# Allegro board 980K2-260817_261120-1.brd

Outline 419.1 x 474.98 mm; copper layers: TOP, L02_GND, L03_DP, L04_GND, L05_DP, L06_GND, L07_VI, L08_GND, L09_VI, L10_GND, L11_VI, L12_GND, L13_VI, L14_GND, L15_5V, L16_5V, L17_C-BIT, L18_C-BIT, L19_GND, L20_VI, L21_GND, L22_VI, L23_GND, L24_VI, L25_GND, L26_VI, L27_GND, L28_DP, L29_GND, L30_DP, L31_GND, BOTTOM. Coordinates in mm from the lower left corner of the outline.

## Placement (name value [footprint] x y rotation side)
BC9  0.1U-50-X-S4-TDK  [C0402]  86.11 107.82 180 bottom
BR5  1K-1-S4  [R0402]  86.11 106.3 0 bottom
BR6  1K-1-S4  [R0402]  86.11 103.5 0 bottom
BR7  0-5-S6  [R0603]  83.44 106.3 180 bottom
BR8  0-5-S4  [R0402]  86.11 105.03 180 bottom
BR9  0-5-S4  [R0402]  86.11 102.24 180 bottom
BU1  AT24C512C-SSHM-T-SOIC8  [SO8_206X127MM]  91.06 105.66 180 bottom
C48  0.01U-100-X7R-S6-MU  [C0603]  147.57 273.87 90 bottom
C49  0.01U-100-X7R-S6-MU  [C0603]  136.27 268.99 270 bottom
C50  0.01U-100-X7R-S6-MU  [C0603]  142.28 268.54 270 bottom
C53  1U-16-X5R-S4-YA  [C0402]  142.24 261.62 270 bottom
C54  2.2U-16-X-S4-MU  [C0402]  136.53 261.62 270 bottom
C58  1U-16-X5R-S4-YA  [C0402]  142.11 257.68 270 bottom
C59  4.7U-100-X-SB-MU  [C1210]  140.59 246.51 270 bottom
C60  0.01U-100-X7R-S6-MU  [C0603]  147.01 259.72 0 bottom
C61  0.01U-100-X7R-S6-MU  [C0603]  156.88 264.78 180 bottom
C62  2.2U-16-X-S4-MU  [C0402]  157.07 259.72 0 bottom
C63  0.01U-100-X7R-S6-MU  [C0603]  157.73 261.82 90 bottom
C64  0.01U-100-X7R-S6-MU  [C0603]  156.88 267.82 180 bottom
C65  0.1U-25-X7R-S4-MU  [C0402]  157.73 271.37 90 bottom
C66  0.1U-25-X7R-S4-MU  [C0402]  152.65 276.61 180 bottom
C67  0.1U-25-X7R-S4-MU  [C0402]  150.24 278.13 180 bottom
C68  0.1U-25-X7R-S4-MU  [C0402]  147.83 282.7 180 bottom
C69  0.01U-100-X7R-S6-MU  [C0603]  151.96 259.72 0 bottom
C70  0.1U-25-X7R-S4-MU  [C0402]  122.8 294.89 180 bottom
C71  0.1U-25-X7R-S4-MU  [C0402]  129.42 294.89 180 bottom
C72  0.1U-25-X7R-S4-MU  [C0402]  158.75 227.33 0 bottom
C73  0.1U-25-X7R-S4-MU  [C0402]  153.67 227.33 0 bottom
C74  0.1U-25-X7R-S4-MU  [C0402]  157.73 273.91 90 bottom
CT1  47U-16-X5R-SB-MU  [C1210]  88.14 153.16 180 bottom
CT2  10U-16-X5R-S8-TY  [C0805]  108.2 164.59 90 bottom
CT3  22U-16-X-S8-MU  [C0805]  110.49 164.59 90 bottom
CT7  47U-16-X5R-SB-MU  [C1210]  88.14 132.84 180 bottom
CT8  10U-16-X5R-S8-TY  [C0805]  110.49 144.27 90 bottom
CT9  22U-16-X-S8-MU  [C0805]  108.2 144.27 90 bottom
F1  C1F8-0.25A-SA  [FUSE_1206_H1P05MM]  88.14 156.72 0 bottom
F2  C1F8-0.25A-SA  [FUSE_1206_H1P05MM]  88.14 136.4 0 bottom
FD1  -  [FD_040_V2]  95.25 123.19 0 top
FD2  -  [FD_040_V2]  323.85 123.19 0 top
FD3  -  [FD_040_V2]  323.85 351.79 0 top
FD4  -  [FD_040_V2]  95.25 351.79 0 top
FD5  -  [FD_040_V2]  323.85 123.19 180 bottom
FD6  -  [FD_040_V2]  95.25 123.19 180 bottom
FD7  -  [FD_040_V2]  95.25 351.79 180 bottom
FD8  -  [FD_040_V2]  323.85 351.79 180 bottom
FD9  -  [FD_040_V2]  19.05 123.19 0 top
FD10  -  [FD_040_V2]  400.05 123.19 0 top
FD11  -  [FD_040_V2]  400.05 351.79 0 top
FD12  -  [FD_040_V2]  19.05 351.79 0 top
FD13  -  [FD_040_V2]  400.05 123.19 180 bottom
FD14  -  [FD_040_V2]  19.05 123.19 180 bottom
FD15  -  [FD_040_V2]  19.05 351.79 180 bottom
FD16  -  [FD_040_V2]  400.05 351.79 180 bottom
K1  UA2-5NJ-A-V3  [RL_NECUA2_5V_V3]  138.43 290.63 270 bottom
K2  G3VM-201DR  [RL_G3VM201DR_200V]  144.15 277.5 0 bottom
K3  G3VM-201DR  [RL_G3VM201DR_200V]  134.49 273.18 90 bottom
K4  G3VM-201DR  [RL_G3VM201DR_200V]  144.15 291.47 0 bottom
K5  G3VM-51UR-5V-VSON4  [RL_G3VM_4P_VSON4]  139.95 268.99 0 bottom
K6  G3VM-51UR-5V-VSON4  [RL_G3VM_4P_VSON4]  139.95 266.19 0 bottom
K7  G3VM-51UR-5V-VSON4  [RL_G3VM_4P_VSON4]  139.95 264.16 0 bottom
K8  G3VM-51UR-5V-VSON4  [RL_G3VM_4P_VSON4]  139.95 261.62 0 bottom
K9  G3VM-51UR-5V-VSON4  [RL_G3VM_4P_VSON4]  134.24 261.62 0 bottom
K10  G3VM-51UR-5V-VSON4  [RL_G3VM_4P_VSON4]  135.38 264.16 0 bottom
K11  G3VM-51UR-5V-VSON4  [RL_G3VM_4P_VSON4]  143.76 257.3 90 bottom
K12  G3VM-51UR-5V-VSON4  [RL_G3VM_4P_VSON4]  143.76 252.48 90 bottom
K13  G3VM-51UR-5V-VSON4  [RL_G3VM_4P_VSON4]  143.76 246.51 90 bottom
K14  G3VM-51UR-5V-VSON4  [RL_G3VM_4P_VSON4]  146.56 252.48 90 bottom
K15  UA2-5NJ-A-V3  [RL_NECUA2_5V_V3]  135.25 242.75 270 bottom
K16  G3VM-51UR-5V-VSON4  [RL_G3VM_4P_VSON4]  146.56 257.3 90 bottom
K17  G3VM-51UR-5V-VSON4  [RL_G3VM_4P_VSON4]  148.72 257.3 90 bottom
K18  G3VM-51UR-5V-VSON4  [RL_G3VM_4P_VSON4]  148.72 252.48 90 bottom
K19  G3VM-51UR-5V-VSON4  [RL_G3VM_4P_VSON4]  151.51 257.3 90 bottom
K20  G3VM-51UR-5V-VSON4  [RL_G3VM_4P_VSON4]  151.51 252.48 90 bottom
K21  G3VM-51UR-5V-VSON4  [RL_G3VM_4P_VSON4]  153.67 257.3 90 bottom
K22  G3VM-51UR-5V-VSON4  [RL_G3VM_4P_VSON4]  153.67 252.48 90 bottom
K23  UA2-5NJ-A-V3  [RL_NECUA2_5V_V3]  152.78 242.75 270 bottom
K24  UA2-5NJ-A-V3  [RL_NECUA2_5V_V3]  161.04 242.75 270 bottom
K25  G3VM-51UR-5V-VSON4  [RL_G3VM_4P_VSON4]  156.97 257.3 90 bottom
K26  G3VM-51UR-5V-VSON4  [RL_G3VM_4P_VSON4]  156.97 252.48 90 bottom
K27  G3VM-51UR-5V-VSON4  [RL_G3VM_4P_VSON4]  160.15 261.37 180 bottom
K28  G3VM-51UR-5V-VSON4  [RL_G3VM_4P_VSON4]  164.72 261.37 180 bottom
K29  G3VM-51UR-5V-VSON4  [RL_G3VM_4P_VSON4]  169.29 261.37 180 bottom
K30  G3VM-51UR-5V-VSON4  [RL_G3VM_4P_VSON4]  160.15 265.18 180 bottom
K31  G3VM-51UR-5V-VSON4  [RL_G3VM_4P_VSON4]  164.72 265.18 180 bottom
K32  G3VM-51UR-5V-VSON4  [RL_G3VM_4P_VSON4]  169.29 265.18 180 bottom
K33  G3VM-51UR-5V-VSON4  [RL_G3VM_4P_VSON4]  160.15 268.22 180 bottom
K34  G3VM-51UR-5V-VSON4  [RL_G3VM_4P_VSON4]  164.72 268.22 180 bottom
K35  G3VM-51UR-5V-VSON4  [RL_G3VM_4P_VSON4]  169.29 268.22 180 bottom
K36  G3VM-51UR-5V-VSON4  [RL_G3VM_4P_VSON4]  160.15 271.27 180 bottom
K37  G3VM-51UR-5V-VSON4  [RL_G3VM_4P_VSON4]  164.72 271.27 180 bottom
K38  G3VM-51UR-5V-VSON4  [RL_G3VM_4P_VSON4]  160.15 273.81 180 bottom
K39  G3VM-51UR-5V-VSON4  [RL_G3VM_4P_VSON4]  164.72 273.81 180 bottom
K40  G3VM-51UR-5V-VSON4  [RL_G3VM_4P_VSON4]  155.58 273.05 270 bottom
K41  G3VM-51UR-5V-VSON4  [RL_G3VM_4P_VSON4]  155.58 277.62 270 bottom
K42  G3VM-51UR-5V-VSON4  [RL_G3VM_4P_VSON4]  155.58 282.19 270 bottom
K43  G3VM-51UR-5V-VSON4  [RL_G3VM_4P_VSON4]  152.65 273.05 270 bottom
K44  G3VM-51UR-5V-VSON4  [RL_G3VM_4P_VSON4]  152.65 278.89 270 bottom
K45  G3VM-51UR-5V-VSON4  [RL_G3VM_4P_VSON4]  152.65 283.46 270 bottom
K46  G3VM-51UR-5V-VSON4  [RL_G3VM_4P_VSON4]  150.24 274.57 270 bottom
K47  G3VM-51UR-5V-VSON4  [RL_G3VM_4P_VSON4]  150.24 280.42 270 bottom
K48  G3VM-51UR-5V-VSON4  [RL_G3VM_4P_VSON4]  150.24 284.99 270 bottom
K49  G3VM-51UR-5V-VSON4  [RL_G3VM_4P_VSON4]  147.83 284.99 270 bottom
K50  G3VM-51UR-5V-VSON4  [RL_G3VM_4P_VSON4]  147.83 279.15 270 bottom
K51  G3VM-51UR-5V-VSON4  [RL_G3VM_4P_VSON4]  148.72 246.51 270 bottom
K52  G3VM-51UR-5V-VSON4  [RL_G3VM_4P_VSON4]  148.72 241.17 90 bottom
K53  G3VM-51UR-5V-VSON4  [RL_G3VM_4P_VSON4]  156.97 246.51 270 bottom
K54  G3VM-51UR-5V-VSON4  [RL_G3VM_4P_VSON4]  156.97 241.17 90 bottom
K55  G3VM-51UR-5V-VSON4  [RL_G3VM_4P_VSON4]  123.44 292.35 0 bottom
K56  G3VM-201DR  [RL_G3VM201DR_200V]  128.4 288.67 90 bottom
K57  G3VM-51UR-5V-VSON4  [RL_G3VM_4P_VSON4]  158.12 234.57 270 bottom
K58  G3VM-51UR-5V-VSON4  [RL_G3VM_4P_VSON4]  156.08 234.57 270 bottom
K59  G3VM-51UR-5V-VSON4  [RL_G3VM_4P_VSON4]  153.04 234.57 270 bottom
K60  G3VM-51UR-5V-VSON4  [RL_G3VM_4P_VSON4]  151 234.57 270 bottom
K61  G3VM-51UR-5V-VSON4  [RL_G3VM_4P_VSON4]  130.05 292.35 0 bottom
LD1  LDG-2-S6  [LED_0603]  88.91 165.19 0 top
LD3  LDG-2-S6  [LED_0603]  88.91 144.87 0 top
LT1  L10U-16A-S16.5X15.5-PU  [IND_16P5X15P5MM]  98.93 156.59 0 bottom
LT3  L10U-16A-S16.5X15.5-PU  [IND_16P5X15P5MM]  98.93 136.27 0 bottom
M1  PG_LTXDX_F_X1_OUTLINE_TD_V2  [PG_LTXDX_F_X1_OUTLINE_TD_COHU]  209.55 237.49 0 top
NOREF  -  []  222.87 286.99 0 top
NOREF#2  -  []  199.22 255.7 90 top
NOREF#3  -  []  272.63 173.69 0 top
NOREF#4  -  []  312.52 456.29 90 top
NOREF#5  -  []  227.43 224.11 90 top
NOREF#6  -  []  252.87 227.4 90 top
NOREF#7  -  []  198.91 172.21 90 top
NOREF#8  -  []  241.44 244.35 0 top
NOREF#9  -  []  250.92 231.95 90 top
NOREF#10  -  []  151.95 178.07 0 top
NOREF#11  -  []  156.57 253.35 0 top
NOREF#12  -  []  203.84 207.82 90 top
NOREF#13  -  []  157.8 14.59 90 top
NOREF#14  -  []  268.78 222.65 0 top
NOREF#15  -  []  272.25 218.02 0 top
NOREF#16  -  []  196.57 245.63 0 top
NOREF#17  -  []  279.44 239.15 0 top
NOREF#18  -  []  195.17 276.75 90 top
NOREF#19  -  []  188.32 182.05 0 top
NOREF#20  -  []  193.98 238.07 0 top
NOREF#21  -  []  277.18 236.17 90 top
NOREF#22  -  []  160.23 176.17 90 top
NOREF#23  -  []  266.01 250.88 90 top
NOREF#24  -  []  179.72 273.6 90 top
NOREF#25  -  []  138.95 206.12 0 top
NOREF#26  -  []  238.11 172.1 0 top
NOREF#27  -  []  220.83 265.79 90 top
NOREF#28  -  []  260.95 266.12 90 top
NOREF#29  -  []  159.06 238.07 0 top
NOREF#30  -  []  209.52 210.32 90 top
NOREF#31  -  []  190.97 179.57 90 top
NOREF#32  -  []  272.63 173.69 90 top
NOREF#33  -  []  220.95 204.09 90 top
NOREF#34  -  []  239.4 214.54 0 top
NOREF#35  -  []  209.55 237.49 90 top
NOREF#36  -  []  195.92 190.88 90 top
NOREF#37  -  []  273.83 172.21 90 top
NOREF#38  -  []  131.22 234.89 90 top
NOREF#39  -  []  148.19 247.71 0 top
NOREF#40  -  []  156.1 271.85 90 top
NOREF#41  -  []  148.32 242.05 0 top
NOREF#42  -  []  235.49 168.7 90 top
NOREF#43  -  []  197.04 184.35 0 top
NOREF#44  -  []  192.72 192.78 0 top
NOREF#45  -  []  272.66 166.36 90 top
NOREF#46  -  []  283.84 201.77 0 top
NOREF#47  -  []  176.83 287.03 0 top
NOREF#48  -  []  168.45 295.2 0 top
NOREF#49  -  []  159.27 205.58 0 top
NOREF#50  -  []  162.88 458.49 0 top
NOREF#51  -  []  195.92 195.7 90 top
NOREF#52  -  []  191.24 197.85 90 top
NOREF#53  -  []  192.63 172.86 0 top
NOREF#54  -  []  226.01 244.91 90 top
NOREF#55  -  []  218.85 241.15 90 top
NOREF#56  -  []  172.55 190.49 90 top
NOREF#57  -  []  164.44 292.28 90 top
NOREF#58  -  []  204.61 294.89 90 top
NOREF#59  -  []  195.17 276.75 0 top
NOREF#60  -  []  243.84 261.77 0 top
NOREF#61  -  []  236.02 181.47 0 top
NOREF#62  -  []  277.37 256.43 90 top
NOREF#63  -  []  209.55 237.49 0 top
NOREF#64  -  []  209.05 292.28 0 top
NOREF#65  -  []  209.52 204.23 90 top
NOREF#66  -  []  234.39 286.59 90 top
NOREF#67  -  []  230.98 244.35 0 top
NOREF#68  -  []  275.56 235.77 0 top
NOREF#69  -  []  194.39 276.17 90 top
NOREF#70  -  []  283.04 176.5 90 top
NOREF#71  -  []  288.42 267.82 90 top
NOREF#72  -  []  279.72 223.79 90 top
NOREF#73  -  []  251.21 234.89 90 top
NOREF#74  -  []  124.11 392.33 90 top
NOREF#75  -  []  241.75 269.17 0 top
NOREF#76  -  []  196.57 182.05 0 top
NOREF#77  -  []  202.85 297.22 0 top
NOREF#78  -  []  201.75 206.13 0 top
NOREF#79  -  []  283.97 274.54 0 top
NOREF#80  -  []  237.04 184.35 0 top
NOREF#81  -  []  146.88 289.79 0 top
NOREF#82  -  []  156.79 171.3 0 top
NOREF#83  -  []  271.98 280.75 90 top
NOREF#84  -  []  269.12 191.6 90 top
NOREF#85  -  []  199.27 211.67 0 top
NOREF#86  -  []  226.83 256.75 0 top
NOREF#87  -  []  141.55 202.57 90 top
NOREF#88  -  []  224.04 245.96 0 top
NOREF#89  -  []  191.98 286.59 90 top
NOREF#90  -  []  155.96 168.6 90 top
NOREF#91  -  []  151.53 173.37 90 top
NOREF#92  -  []  234.39 222.02 90 top
NOREF#93  -  []  262.81 257.6 0 top
NOREF#94  -  []  140.43 224.38 90 top
NOREF#95  -  []  213.24 201.55 0 top
NOREF#96  -  []  192.51 235.77 0 top
NOREF#97  -  []  226.7 237.02 90 top
NOREF#98  -  []  239.27 270.87 90 top
NOREF#99  -  []  254.09 267.27 90 top
NOREF#100  -  []  152.25 212.18 90 top
NOREF#101  -  []  179.08 201.22 0 top
NOREF#102  -  []  163.97 264.45 90 top
NOREF#103  -  []  279.4 260.64 90 top
NOREF#104  -  []  191.73 172.54 0 top
NOREF#105  -  []  230.41 168.7 90 top
NOREF#106  -  []  189.72 226.19 0 top
NOREF#107  -  []  261.85 306.46 0 top
NOREF#108  -  []  95.33 18.69 0 top
NOREF#109  -  []  220.83 205.79 90 top
NOREF#110  -  []  163.97 213.09 90 top
NOREF#111  -  []  156.33 167.9 90 top
NOREF#112  -  []  185.61 257.6 0 top
NOREF#113  -  []  127.04 239.09 0 top
NOREF#114  -  []  276.61 173.37 90 top
NOREF#115  -  []  179.73 178.35 0 top
NOREF#116  -  []  151.91 191.6 90 top
NOREF#117  -  []  139.55 294.49 0 top
NOREF#118  -  []  155.68 173.69 90 top
NOREF#119  -  []  193.6 286.96 0 top
NOREF#120  -  []  237.25 191.93 0 top
NOREF#121  -  []  218.95 208.91 0 top
NOREF#122  -  []  279.22 195.7 90 top
NOREF#123  -  []  239.4 200.64 90 top
NOREF#124  -  []  190.88 228.6 90 top
NOREF#125  -  []  289.52 212.86 90 top
NOREF#126  -  []  270.97 250.88 90 top
NOREF#127  -  []  228.35 223.79 90 top
NOREF#128  -  []  258.95 264.09 0 top
NOREF#129  -  []  271.11 193.35 0 top
NOREF#130  -  []  283.97 207.5 90 top
NOREF#131  -  []  149.55 188.99 90 top
NOREF#132  -  []  219.08 201.22 0 top
NOREF#133  -  []  268.44 257.85 90 top
NOREF#134  -  []  231.53 233.37 90 top
NOREF#135  -  []  228.78 244.35 0 top
NOREF#136  -  []  197.71 173.69 0 top
NOREF#137  -  []  153.18 271.85 90 top
NOREF#138  -  []  243.84 204.78 90 top
NOREF#139  -  []  268.78 184.35 0 top
NOREF#140  -  []  244.32 291.95 90 top
NOREF#141  -  []  149.29 279.37 0 top
NOREF#142  -  []  294.99 82.65 0 top
NOREF#143  -  []  267.77 257.6 0 top
NOREF#144  -  []  206.32 274.76 0 top
NOREF#145  -  []  165.38 286.23 0 top
NOREF#146  -  []  132.26 248.4 0 top
NOREF#147  -  []  159.4 212 0 top
NOREF#148  -  []  169.52 210.32 90 top
NOREF#149  -  []  214.51 203.76 0 top
NOREF#150  -  []  196.1 211.85 90 top
NOREF#151  -  []  146.83 191.93 0 top
NOREF#152  -  []  218.95 206.12 0 top
NOREF#153  -  []  172.87 287.4 90 top
NOREF#154  -  []  152.46 247.68 90 top
NOREF#155  -  []  273.18 184.35 0 top
NOREF#156  -  []  58.41 375.29 0 top
NOREF#157  -  []  222.81 197.6 0 top
NOREF#158  -  []  293.99 17.15 90 top
NOREF#159  -  []  193.27 253.35 0 top
NOREF#160  -  []  186.28 253.03 90 top
NOREF#161  -  []  219.55 180.49 90 top
NOREF#162  -  []  237.25 240.62 0 top
NOREF#163  -  []  146.28 193.03 90 top
NOREF#164  -  []  163.84 267.82 90 top
NOREF#165  -  []  309.55 14.59 90 top
NOREF#166  -  []  275.68 173.69 0 top
NOREF#167  -  []  175.11 261.22 90 top
NOREF#168  -  []  243.97 274.54 0 top
NOREF#169  -  []  290.89 209.17 0 top
NOREF#170  -  []  150.41 228.7 90 top
NOREF#171  -  []  271.19 228.49 0 top
NOREF#172  -  []  150.77 279.22 90 top
NOREF#173  -  []  278.91 232.21 90 top
NOREF#174  -  []  182.87 286.99 0 top
NOREF#175  -  []  197.92 250.01 0 top
NOREF#176  -  []  283.04 236.5 90 top
NOREF#177  -  []  270.77 219.22 90 top
NOREF#178  -  []  268.32 185.63 90 top
NOREF#179  -  []  140.59 184.98 90 top
NOREF#180  -  []  269.72 281.62 0 top
NOREF#181  -  []  181.6 308.11 0 top
NOREF#182  -  []  130.02 214.45 0 top
NOREF#183  -  []  276.02 181.47 0 top
NOREF#184  -  []  193.76 195.7 90 top
NOREF#185  -  []  243.84 273.41 90 top
NOREF#186  -  []  152.51 235.77 0 top
NOREF#187  -  []  144.71 241.71 90 top
NOREF#188  -  []  181.55 267.14 90 top
NOREF#189  -  []  181.55 265.11 90 top
NOREF#190  -  []  163.84 274.21 0 top
NOREF#191  -  []  129.17 291.95 0 top
NOREF#192  -  []  199.4 205.9 0 top
NOREF#193  -  []  254.09 200.42 90 top
NOREF#194  -  []  147.77 197.6 0 top
NOREF#195  -  []  197.37 251.6 90 top
NOREF#196  -  []  228.32 185.63 90 top
NOREF#197  -  []  218.95 264.09 0 top
NOREF#198  -  []  148.99 240.62 0 top
NOREF#199  -  []  149.67 190.01 0 top
NOREF#200  -  []  271.76 227.33 0 top
NOREF#201  -  []  199.4 260.64 90 top
NOREF#202  -  []  272.72 197.6 0 top
NOREF#203  -  []  199.22 195.7 90 top
NOREF#204  -  []  236.81 232.54 0 top
NOREF#205  -  []  197.03 238.07 0 top
NOREF#206  -  []  288.54 202.09 0 top
NOREF#207  -  []  181.55 207.14 90 top
NOREF#208  -  []  147.3 220.35 0 top
NOREF#209  -  []  276.7 181.72 90 top
NOREF#210  -  []  188.99 251.93 0 top
NOREF#211  -  []  271.95 238.07 0 top
NOREF#212  -  []  146.7 237.02 90 top
NOREF#213  -  []  269.72 215.77 0 top
NOREF#214  -  []  145.61 252.5 0 top
NOREF#215  -  []  197.47 17.15 90 top
NOREF#216  -  []  227.43 284.11 0 top
NOREF#217  -  []  271.24 253.03 90 top
NOREF#218  -  []  225.41 213.02 90 top
NOREF#219  -  []  264.26 396.29 0 top
NOREF#220  -  []  216.55 220.49 0 top
NOREF#221  -  []  266.69 297.01 90 top
NOREF#222  -  []  159.27 270.87 90 top
NOREF#223  -  []  229.84 213.7 90 top
NOREF#224  -  []  156.57 245.63 0 top
NOREF#225  -  []  179.08 263.76 0 top
NOREF#226  -  []  148.78 244.35 0 top
NOREF#227  -  []  195.05 278.82 0 top
NOREF#228  -  []  232.13 280.09 0 top
NOREF#229  -  []  191.87 456.29 90 top
NOREF#230  -  []  266.16 198.18 0 top
NOREF#231  -  []  151.19 228.49 0 top
NOREF#232  -  []  264.26 456.29 90 top
NOREF#233  -  []  215.65 244.35 0 top
NOREF#234  -  []  219.73 178.35 0 top
NOREF#235  -  []  89.76 145.32 0 top
NOREF#236  -  []  266.43 296.46 90 top
NOREF#237  -  []  165.38 286.23 0 top
NOREF#238  -  []  231.98 286.59 90 top
NOREF#239  -  []  203.4 236.38 0 top
NOREF#240  -  []  283.97 200.64 90 top
NOREF#241  -  []  194.33 264.33 90 top
NOREF#242  -  []  234.39 276.17 90 top
NOREF#243  -  []  234.07 256.43 90 top
NOREF#244  -  []  243.97 273.09 90 top
NOREF#245  -  []  195.68 173.69 0 top
NOREF#246  -  []  276.54 167 0 top
NOREF#247  -  []  178.95 208.91 0 top
NOREF#248  -  []  153.27 193.35 0 top
NOREF#249  -  []  242.2 238.35 0 top
NOREF#250  -  []  271.11 253.35 0 top
NOREF#251  -  []  136.28 307.18 0 top
NOREF#252  -  []  239.44 179.15 0 top
NOREF#253  -  []  191.98 226.59 90 top
NOREF#254  -  []  256.83 227.03 0 top
NOREF#255  -  []  199.72 223.79 90 top
NOREF#256  -  []  152.25 272.17 0 top
NOREF#257  -  []  294.09 264.23 90 top
NOREF#258  -  []  173.45 244.35 0 top
NOREF#259  -  []  149.72 275.77 0 top
NOREF#260  -  []  162.87 16.49 0 top
NOREF#261  -  []  218.35 209.04 0 top
NOREF#262  -  []  219.08 268.59 0 top
NOREF#263  -  []  254.09 204.23 90 top
NOREF#264  -  []  261.59 294.14 0 top
NOREF#265  -  []  268.78 288.49 0 top
NOREF#266  -  []  173.78 267.01 0 top
NOREF#267  -  []  267.05 209.24 0 top
NOREF#268  -  []  231.91 191.6 90 top
NOREF#269  -  []  229.72 226.19 0 top
NOREF#270  -  []  196.7 241.72 90 top
NOREF#271  -  []  261.55 269.94 90 top
NOREF#272  -  []  186.01 244.91 90 top
NOREF#273  -  []  183.36 193.35 0 top
NOREF#274  -  []  193.76 250.88 90 top
NOREF#275  -  []  147.9 205.84 90 top
NOREF#276  -  []  272.51 175.77 0 top
NOREF#277  -  []  230.77 223.79 90 top
NOREF#278  -  []  232.25 222.59 0 top
NOREF#279  -  []  267.05 269.24 0 top
NOREF#280  -  []  151.11 258.18 0 top
NOREF#281  -  []  215.11 261.22 90 top
NOREF#282  -  []  180.95 204.09 90 top
NOREF#283  -  []  151.79 191.93 0 top
NOREF#284  -  []  273.03 172.1 0 top
NOREF#285  -  []  151.7 277.85 0 top
NOREF#286  -  []  195.17 281.32 90 top
NOREF#287  -  []  196.79 171.3 0 top
NOREF#288  -  []  159.4 260.64 90 top
NOREF#289  -  []  275.17 281.32 90 top
NOREF#290  -  []  192.25 222.59 90 top
NOREF#291  -  []  231.19 218.07 0 top
NOREF#292  -  []  147.3 280.35 0 top
NOREF#293  -  []  187.43 278.27 90 top
NOREF#294  -  []  186.96 251.6 90 top
NOREF#295  -  []  232.25 282.59 90 top
NOREF#296  -  []  142.81 241.71 0 top
NOREF#297  -  []  233.6 282.39 0 top
NOREF#298  -  []  199.4 204.45 90 top
NOREF#299  -  []  231.11 198.18 0 top
NOREF#300  -  []  228.99 191.93 0 top
NOREF#301  -  []  146.83 256.75 0 top
NOREF#302  -  []  170.89 206.13 0 top
NOREF#303  -  []  286.32 214.76 0 top
NOREF#304  -  []  286.32 212.22 0 top
NOREF#305  -  []  272.25 212.18 0 top
NOREF#306  -  []  286.32 266.13 0 top
NOREF#307  -  []  218.83 232.23 0 top
NOREF#308  -  []  148.78 222.65 0 top
NOREF#309  -  []  176.55 280.49 0 top
NOREF#310  -  []  233.76 250.88 90 top
NOREF#311  -  []  157.71 173.69 0 top
NOREF#312  -  []  271.76 167.33 0 top
NOREF#313  -  []  139.08 263.76 0 top
NOREF#314  -  []  188.19 247.71 0 top
NOREF#315  -  []  227.03 231.4 0 top
NOREF#316  -  []  167.04 239.09 0 top
NOREF#317  -  []  210.89 206.13 0 top
NOREF#318  -  []  187.99 238.35 0 top
NOREF#319  -  []  180.43 224.38 90 top
NOREF#320  -  []  157.04 244.35 0 top
NOREF#321  -  []  284.95 272.86 90 top
NOREF#322  -  []  255.11 201.22 90 top
NOREF#323  -  []  248.45 295.2 0 top
NOREF#324  -  []  208.42 260.97 90 top
NOREF#325  -  []  188.78 184.35 0 top
NOREF#326  -  []  214.43 292.23 0 top
NOREF#327  -  []  241.75 274.76 0 top
NOREF#328  -  []  138.95 261.55 0 top
NOREF#329  -  []  136.5 271.94 90 top
NOREF#330  -  []  232.25 272.17 0 top
NOREF#331  -  []  193.03 172.1 0 top
NOREF#332  -  []  89.76 164.74 90 top
NOREF#333  -  []  139.55 240.49 90 top
NOREF#334  -  []  220.59 244.98 90 top
NOREF#335  -  []  132.55 190.49 90 top
NOREF#336  -  []  261.59 308.11 0 top
NOREF#337  -  []  181.85 292.49 0 top
NOREF#338  -  []  156.02 247.68 0 top
NOREF#339  -  []  276.8 280.49 90 top
NOREF#340  -  []  156.81 232.54 0 top
NOREF#341  -  []  135.43 276.18 0 top
NOREF#342  -  []  164.95 207.27 90 top
NOREF#343  -  []  283.97 205.9 0 top
NOREF#344  -  []  163.97 273.09 90 top
NOREF#345  -  []  155.78 237.5 90 top
NOREF#346  -  []  266.83 256.75 0 top
NOREF#347  -  []  275.05 214.25 0 top
NOREF#348  -  []  161.84 295.2 0 top
NOREF#349  -  []  239.4 202.09 0 top
NOREF#350  -  []  192.63 232.86 0 top
NOREF#351  -  []  156.33 227.9 90 top
NOREF#352  -  []  219.73 238.35 0 top
NOREF#353  -  []  268.81 250.88 90 top
NOREF#354  -  []  199.27 200.97 90 top
NOREF#355  -  []  133.36 261.22 0 top
NOREF#356  -  []  227.3 220.35 0 top
NOREF#357  -  []  197.47 17.15 0 top
NOREF#358  -  []  228.35 217.95 90 top
NOREF#359  -  []  192.72 252.78 0 top
NOREF#360  -  []  276.7 253.03 90 top
NOREF#361  -  []  266.96 191.6 90 top
NOREF#362  -  []  155.56 235.77 0 top
NOREF#363  -  []  270.15 266.89 90 top
NOREF#364  -  []  220.95 266.12 90 top
NOREF#365  -  []  150.63 259.3 0 top
NOREF#366  -  []  159.06 178.07 0 top
NOREF#367  -  []  288.54 265.9 0 top
NOREF#368  -  []  246.32 274.76 0 top
NOREF#369  -  []  277.37 191.6 90 top
NOREF#370  -  []  226.01 184.91 90 top
NOREF#371  -  []  134.04 210.63 90 top
NOREF#372  -  []  151.7 283.69 0 top
NOREF#373  -  []  159.4 273.09 90 top
NOREF#374  -  []  193.6 226.96 0 top
NOREF#375  -  []  318.12 17.15 0 top
NOREF#376  -  []  149.29 282.02 90 top
NOREF#377  -  []  138.95 268.91 0 top
NOREF#378  -  []  232.13 224.66 0 top
NOREF#379  -  []  159.4 268.95 0 top
NOREF#380  -  []  227.77 257.6 0 top
NOREF#381  -  []  283.84 213.41 90 top
NOREF#382  -  []  211.21 294.89 90 top
NOREF#383  -  []  239.27 200.97 90 top
NOREF#384  -  []  239.44 239.15 0 top
NOREF#385  -  []  277.25 251.93 0 top
NOREF#386  -  []  250.89 262.32 0 top
NOREF#387  -  []  159.72 223.79 90 top
NOREF#388  -  []  288.42 260.97 90 top
NOREF#389  -  []  231.19 223.92 0 top
NOREF#390  -  []  277.5 245.31 90 top
NOREF#391  -  []  283.97 264.45 90 top
NOREF#392  -  []  137.28 272.5 90 top
NOREF#393  -  []  214.43 232.23 0 top
NOREF#394  -  []  279.4 210.55 90 top
NOREF#395  -  []  155.68 233.69 0 top
NOREF#396  -  []  155.17 281.32 90 top
NOREF#397  -  []  152.63 233.69 0 top
NOREF#398  -  []  268.44 181.72 90 top
NOREF#399  -  []  219.73 178.35 0 top
NOREF#400  -  []  106.83 127.87 90 top
NOREF#401  -  []  199.27 207.82 90 top
NOREF#402  -  []  137.28 286.47 90 top
NOREF#403  -  []  164.95 270.32 90 top
NOREF#404  -  []  236.38 181.15 90 top
NOREF#405  -  []  192.51 175.77 0 top
NOREF#406  -  []  167.98 226.38 90 top
NOREF#407  -  []  294.09 204.23 90 top
NOREF#408  -  []  209.49 220.89 0 top
NOREF#409  -  []  199.4 213.09 90 top
NOREF#410  -  []  262.87 213.02 0 top
NOREF#411  -  []  225 456.29 0 top
NOREF#412  -  []  194.39 286.59 90 top
NOREF#413  -  []  171.22 234.89 90 top
NOREF#414  -  []  185.41 226.99 90 top
NOREF#415  -  []  136.26 263.76 90 top
NOREF#416  -  []  196.57 258.18 0 top
NOREF#417  -  []  156.02 248.11 90 top
NOREF#418  -  []  243.84 205.58 0 top
NOREF#419  -  []  203.97 264.45 90 top
NOREF#420  -  []  190.56 257.6 0 top
NOREF#421  -  []  192.63 173.69 90 top
NOREF#422  -  []  83.04 144.22 90 top
NOREF#423  -  []  201.75 214.76 0 top
NOREF#424  -  []  155.17 276.75 90 top
NOREF#425  -  []  227.99 178.35 0 top
NOREF#426  -  []  186.43 222.5 90 top
NOREF#427  -  []  195.68 233.69 0 top
NOREF#428  -  []  143.36 253.35 0 top
NOREF#429  -  []  180.83 205.79 90 top
NOREF#430  -  []  233.18 184.35 0 top
NOREF#431  -  []  143.61 456.29 90 top
NOREF#432  -  []  174.09 200.42 90 top
NOREF#433  -  []  153.56 233.37 90 top
NOREF#434  -  []  271.73 172.54 0 top
NOREF#435  -  []  199.22 190.88 90 top
NOREF#436  -  []  234.33 267.37 90 top
NOREF#437  -  []  228.32 245.63 90 top
NOREF#438  -  []  175.24 201.55 90 top
NOREF#439  -  []  190.56 192.78 0 top
NOREF#440  -  []  161.41 167.9 90 top
NOREF#441  -  []  191.24 253.03 90 top
NOREF#442  -  []  168.42 208.62 0 top
NOREF#443  -  []  201.41 167.9 90 top
NOREF#444  -  []  192.63 233.69 90 top
NOREF#445  -  []  159.27 208.62 0 top
NOREF#446  -  []  235.58 202.67 90 top
NOREF#447  -  []  146.16 253.35 0 top
NOREF#448  -  []  265.61 192.78 0 top
NOREF#449  -  []  226.16 212.17 90 top
NOREF#450  -  []  156.38 241.15 90 top
NOREF#451  -  []  233.56 173.37 90 top
NOREF#452  -  []  279.27 267.82 90 top
NOREF#453  -  []  184.04 191.93 0 top
NOREF#454  -  []  232.51 235.77 0 top
NOREF#455  -  []  237.37 240.3 90 top
NOREF#456  -  []  117.23 452.29 90 top
NOREF#457  -  []  249.17 291.95 0 top
NOREF#458  -  []  257.29 187.78 0 top
NOREF#459  -  []  289.52 272.86 90 top
NOREF#460  -  []  284.95 204.23 90 top
NOREF#461  -  []  158.04 228.3 0 top
NOREF#462  -  []  85.84 137.3 0 top
NOREF#463  -  []  150.6 173.69 90 top
NOREF#464  -  []  170.02 274.45 0 top
NOREF#465  -  []  248.42 265.58 0 top
NOREF#466  -  []  164.95 264.23 90 top
NOREF#467  -  []  277.59 235.77 0 top
NOREF#468  -  []  147.77 236.37 0 top
NOREF#469  -  []  186.01 190.88 90 top
NOREF#470  -  []  273.39 193.03 90 top
NOREF#471  -  []  267.99 238.35 0 top
NOREF#472  -  []  156.7 193.03 90 top
NOREF#473  -  []  156.7 253.03 90 top
NOREF#474  -  []  194.33 207.37 90 top
NOREF#475  -  []  284.95 212.86 90 top
NOREF#476  -  []  193.95 191.93 0 top
NOREF#477  -  []  235.17 281.32 90 top
NOREF#478  -  []  186.7 223.05 90 top
NOREF#479  -  []  154.63 282.42 0 top
NOREF#480  -  []  138.95 266.12 0 top
NOREF#481  -  []  149.24 245.31 90 top
NOREF#482  -  []  187.45 269.24 0 top
NOREF#483  -  []  236.57 245.63 0 top
NOREF#484  -  []  277.92 190.01 0 top
NOREF#485  -  []  286.32 272.22 0 top
NOREF#486  -  []  183.36 258.18 0 top
NOREF#487  -  []  279.27 205.58 0 top
NOREF#488  -  []  167.95 226.12 90 top
NOREF#489  -  []  114.62 458.49 0 top
NOREF#490  -  []  201.44 184.35 0 top
NOREF#491  -  []  154.33 264.33 90 top
NOREF#492  -  []  181.55 209.94 90 top
NOREF#493  -  []  146.28 197.85 90 top
NOREF#494  -  []  273.18 271.85 90 top
NOREF#495  -  []  139.49 266.31 90 top
NOREF#496  -  []  158.11 232.1 0 top
NOREF#497  -  []  216 396.29 0 top
NOREF#498  -  []  186.7 283.04 90 top
NOREF#499  -  []  259.55 180.49 90 top
NOREF#500  -  []  193.76 255.7 90 top
NOREF#501  -  []  252.55 190.49 90 top
NOREF#502  -  []  197.25 251.93 0 top
NOREF#503  -  []  149.84 284.11 90 top
NOREF#504  -  []  192.13 214.25 0 top
NOREF#505  -  []  272.13 224.66 0 top
NOREF#506  -  []  270.97 179.57 90 top
NOREF#507  -  []  153.18 244.35 0 top
NOREF#508  -  []  196.52 221.12 0 top
NOREF#509  -  []  209.55 237.49 90 top
NOREF#510  -  []  189.84 284.11 90 top
NOREF#511  -  []  203.97 212 0 top
NOREF#512  -  []  258.35 204.47 0 top
NOREF#513  -  []  233.39 257.85 90 top
NOREF#514  -  []  148.32 182.05 0 top
NOREF#515  -  []  218.95 268.91 0 top
NOREF#516  -  []  197.18 236.17 90 top
NOREF#517  -  []  244.32 231.95 90 top
NOREF#518  -  []  202.2 238.35 0 top
NOREF#519  -  []  235.68 173.69 90 top
NOREF#520  -  []  203.84 201.77 0 top
NOREF#521  -  []  208.54 260.64 90 top
NOREF#522  -  []  238.64 233.37 90 top
NOREF#523  -  []  163.84 205.58 0 top
NOREF#524  -  []  188.35 283.79 90 top
NOREF#525  -  []  294.09 207.27 90 top
NOREF#526  -  []  275.56 175.77 0 top
NOREF#527  -  []  172.55 224.49 0 top
NOREF#528  -  []  196.02 197.6 0 top
NOREF#529  -  []  140.95 206.12 90 top
NOREF#530  -  []  140.83 208.59 90 top
NOREF#531  -  []  150.48 175.77 0 top
NOREF#532  -  []  276.7 241.72 90 top
NOREF#533  -  []  239.22 179.57 90 top
NOREF#534  -  []  155.97 21.69 90 top
NOREF#535  -  []  260.83 261.22 90 top
NOREF#536  -  []  134.51 263.76 0 top
NOREF#537  -  []  149.72 286.19 0 top
NOREF#538  -  []  154.63 283.79 90 top
NOREF#539  -  []  133.24 261.55 0 top
NOREF#540  -  []  221.59 294.14 0 top
NOREF#541  -  []  233.18 282.26 90 top
NOREF#542  -  []  234.07 251.6 90 top
NOREF#543  -  []  182.81 246.81 0 top
NOREF#544  -  []  201.75 202.32 0 top
NOREF#545  -  []  184.04 196.75 0 top
NOREF#546  -  []  149.21 17.15 0 top
NOREF#547  -  []  279.27 201.77 0 top
NOREF#548  -  []  147.77 251.31 0 top
NOREF#549  -  []  199.06 178.07 0 top
NOREF#550  -  []  281.75 212.22 0 top
NOREF#551  -  []  243.84 268.62 0 top
NOREF#552  -  []  227.45 269.24 0 top
NOREF#553  -  []  134.43 292.23 0 top
NOREF#554  -  []  243.04 236.5 90 top
NOREF#555  -  []  114.55 316.49 0 top
NOREF#556  -  []  219.72 273.6 90 top
NOREF#557  -  []  228.32 193.35 0 top
NOREF#558  -  []  242.44 292.28 0 top
NOREF#559  -  []  147.43 218.27 0 top
NOREF#560  -  []  203.1 18.69 90 top
NOREF#561  -  []  277.25 240.62 0 top
NOREF#562  -  []  163.97 205.9 0 top
NOREF#563  -  []  243.97 262.09 0 top
NOREF#564  -  []  270.15 206.89 90 top
NOREF#565  -  []  270.98 184.35 0 top
NOREF#566  -  []  239.27 273.41 90 top
NOREF#567  -  []  254.09 207.27 90 top
NOREF#568  -  []  230.88 168.6 90 top
NOREF#569  -  []  213.36 201.22 0 top
NOREF#570  -  []  205.38 226.23 0 top
NOREF#571  -  []  209.55 237.49 0 top
NOREF#572  -  []  236.7 197.85 90 top
NOREF#573  -  []  217.29 187.78 0 top
NOREF#574  -  []  201.75 209.17 0 top
NOREF#575  -  []  185.09 197.49 90 top
NOREF#576  -  []  168.54 205.9 0 top
NOREF#577  -  []  264.16 245.63 90 top
NOREF#578  -  []  150.77 273.37 90 top
NOREF#579  -  []  161.75 274.76 0 top
NOREF#580  -  []  157.71 233.69 90 top
NOREF#581  -  []  266.69 283.04 90 top
NOREF#582  -  []  258.95 201.55 0 top
NOREF#583  -  []  266.01 244.91 90 top
NOREF#584  -  []  148.35 277.95 90 top
NOREF#585  -  []  129.44 260.67 0 top
NOREF#586  -  []  273.94 251.93 0 top
NOREF#587  -  []  268.78 282.65 0 top
NOREF#588  -  []  223.49 187.06 90 top
NOREF#589  -  []  159.4 272 0 top
NOREF#590  -  []  256.98 265.11 90 top
NOREF#591  -  []  226.43 222.5 90 top
NOREF#592  -  []  191.11 198.18 0 top
NOREF#593  -  []  216.98 265.11 90 top
NOREF#594  -  []  193.6 276.55 0 top
NOREF#595  -  []  259.08 201.22 0 top
NOREF#596  -  []  279.4 262.09 0 top
NOREF#597  -  []  163.97 270.55 90 top
NOREF#598  -  []  203.97 202.09 0 top
NOREF#599  -  []  226.7 223.05 90 top
NOREF#600  -  []  189.72 286.19 0 top
NOREF#601  -  []  147.3 226.19 0 top
NOREF#602  -  []  155.05 214.25 0 top
NOREF#603  -  []  190.97 190.88 90 top
NOREF#604  -  []  283.84 273.41 90 top
NOREF#605  -  []  263.49 257.85 90 top
NOREF#606  -  []  187.77 257.6 0 top
NOREF#607  -  []  193.18 277.69 90 top
NOREF#608  -  []  187.01 458.49 0 top
NOREF#609  -  []  145.42 273.02 90 top
NOREF#610  -  []  135.15 265.24 90 top
NOREF#611  -  []  149.84 213.7 90 top
NOREF#612  -  []  146.17 212.17 90 top
NOREF#613  -  []  189.72 275.77 0 top
NOREF#614  -  []  230.88 228.6 90 top
NOREF#615  -  []  135.24 261.55 90 top
NOREF#616  -  []  239.4 210.55 90 top
NOREF#617  -  []  171.05 229.49 0 top
NOREF#618  -  []  129.17 231.95 0 top
NOREF#619  -  []  171.22 234.24 90 top
NOREF#620  -  []  239.72 214.65 90 top
NOREF#621  -  []  228.44 241.72 90 top
NOREF#622  -  []  276.52 281.12 0 top
NOREF#623  -  []  188.78 244.35 0 top
NOREF#624  -  []  156.45 187.71 0 top
NOREF#625  -  []  241.41 227.9 90 top
NOREF#626  -  []  243.97 205.9 0 top
NOREF#627  -  []  157.03 178.07 0 top
NOREF#628  -  []  239.27 211.67 0 top
NOREF#629  -  []  239.4 264.45 90 top
NOREF#630  -  []  152.51 175.77 0 top
NOREF#631  -  []  239.65 272.56 0 top
NOREF#632  -  []  156.57 242.05 0 top
NOREF#633  -  []  208.42 264.78 90 top
NOREF#634  -  []  174.43 232.23 0 top
NOREF#635  -  []  193.6 216.55 0 top
NOREF#636  -  []  146.88 283.95 0 top
NOREF#637  -  []  154.33 204.33 90 top
NOREF#638  -  []  267.8 205.39 90 top
NOREF#639  -  []  260.95 201.55 90 top
NOREF#640  -  []  140.83 268.59 90 top
NOREF#641  -  []  188.32 242.05 0 top
NOREF#642  -  []  273.27 193.35 0 top
NOREF#643  -  []  216 456.29 0 top
NOREF#644  -  []  230.97 190.88 90 top
NOREF#645  -  []  186.01 250.88 90 top
NOREF#646  -  []  248.54 208.95 0 top
NOREF#647  -  []  152.25 218.02 0 top
NOREF#648  -  []  266.16 212.17 90 top
NOREF#649  -  []  184.16 196.43 90 top
NOREF#650  -  []  156.8 225.06 90 top
NOREF#651  -  []  233.6 216.55 0 top
NOREF#652  -  []  237.71 172.86 0 top
NOREF#653  -  []  151.19 223.92 0 top
NOREF#654  -  []  180.83 208.59 90 top
NOREF#655  -  []  203.84 274.21 0 top
NOREF#656  -  []  161.44 184.35 0 top
NOREF#657  -  []  243.84 265.58 0 top
NOREF#658  -  []  236.54 227 0 top
NOREF#659  -  []  146.83 251.93 0 top
NOREF#660  -  []  195.17 221.32 0 top
NOREF#661  -  []  195.17 212.18 90 top
NOREF#662  -  []  150.88 168.6 90 top
NOREF#663  -  []  284.95 270.32 90 top
NOREF#664  -  []  133.36 201.22 0 top
NOREF#665  -  []  189.84 279.54 90 top
NOREF#666  -  []  182.87 226.99 0 top
NOREF#667  -  []  185.42 274.72 90 top
NOREF#668  -  []  180.95 266.12 90 top
NOREF#669  -  []  279.72 283.79 90 top
NOREF#670  -  []  193.27 258.18 0 top
NOREF#671  -  []  234.33 207.37 90 top
NOREF#672  -  []  323.77 454.29 90 top
NOREF#673  -  []  209.05 232.28 0 top
NOREF#674  -  []  151.7 280.49 90 top
NOREF#675  -  []  188.32 245.63 0 top
NOREF#676  -  []  241.12 188.11 90 top
NOREF#677  -  []  261.55 262.57 90 top
NOREF#678  -  []  151.24 193.03 90 top
NOREF#679  -  []  173.34 17.15 0 top
NOREF#680  -  []  214.04 210.63 90 top
NOREF#681  -  []  236.52 225.69 0 top
NOREF#682  -  []  248.54 268.95 0 top
NOREF#683  -  []  276.1 211.85 90 top
NOREF#684  -  []  139.08 201.22 0 top
NOREF#685  -  []  188.32 258.18 0 top
NOREF#686  -  []  264.04 191.93 0 top
NOREF#687  -  []  212.64 264.47 0 top
NOREF#688  -  []  231.46 167 0 top
NOREF#689  -  []  148.44 241.72 90 top
NOREF#690  -  []  239.4 273.09 90 top
NOREF#691  -  []  289.52 207.27 90 top
NOREF#692  -  []  227.43 278.27 0 top
NOREF#693  -  []  139.73 178.35 0 top
NOREF#694  -  []  156.52 221.12 0 top
NOREF#695  -  []  157.25 180.62 0 top
NOREF#696  -  []  196.02 181.47 0 top
NOREF#697  -  []  255.11 261.22 90 top
NOREF#698  -  []  232.25 278.02 90 top
NOREF#699  -  []  274.78 176.5 90 top
NOREF#700  -  []  147.05 269.24 0 top
NOREF#701  -  []  250.89 202.32 0 top
NOREF#702  -  []  246.32 269.17 0 top
NOREF#703  -  []  149.12 180.3 90 top
NOREF#704  -  []  163.84 204.78 90 top
NOREF#705  -  []  263.36 193.35 0 top
NOREF#706  -  []  128.94 221.73 0 top
NOREF#707  -  []  154.39 216.17 90 top
NOREF#708  -  []  239.27 205.58 0 top
NOREF#709  -  []  169.17 231.95 0 top
NOREF#710  -  []  146.43 222.5 90 top
NOREF#711  -  []  152.72 192.78 0 top
NOREF#712  -  []  147.99 178.35 0 top
NOREF#713  -  []  163.84 200.97 90 top
NOREF#714  -  []  227.23 18.69 90 top
NOREF#715  -  []  175.84 202.57 90 top
NOREF#716  -  []  267.77 192.78 0 top
NOREF#717  -  []  226.28 193.03 90 top
NOREF#718  -  []  159.27 204.78 90 top
NOREF#719  -  []  119.48 456.29 90 top
NOREF#720  -  []  265.61 252.78 0 top
NOREF#721  -  []  189.72 215.77 0 top
NOREF#722  -  []  156.1 216.42 90 top
NOREF#723  -  []  259.73 238.35 0 top
NOREF#724  -  []  153.98 178.07 0 top
NOREF#725  -  []  277.03 178.07 0 top
NOREF#726  -  []  148.32 258.18 0 top
NOREF#727  -  []  226.83 251.93 0 top
NOREF#728  -  []  163.84 211.67 0 top
NOREF#729  -  []  266.16 200.17 90 top
NOREF#730  -  []  250.89 209.17 0 top
NOREF#731  -  []  248.42 267.82 90 top
NOREF#732  -  []  199.4 264.45 90 top
NOREF#733  -  []  118.64 291.4 90 top
NOREF#734  -  []  149.29 289.79 0 top
NOREF#735  -  []  273.6 222.39 0 top
NOREF#736  -  []  270.56 257.6 0 top
NOREF#737  -  []  178.95 264.09 0 top
NOREF#738  -  []  283.84 270.87 90 top
NOREF#739  -  []  123.92 289.94 0 top
NOREF#740  -  []  237.04 244.35 0 top
NOREF#741  -  []  241.75 262.32 0 top
NOREF#742  -  []  230.15 266.89 90 top
NOREF#743  -  []  243.84 211.67 0 top
NOREF#744  -  []  155.56 175.77 0 top
NOREF#745  -  []  119.48 396.29 0 top
NOREF#746  -  []  193.18 244.35 0 top
NOREF#747  -  []  195.17 272.17 90 top
NOREF#748  -  []  218.35 269.04 0 top
NOREF#749  -  []  186.83 196.75 0 top
NOREF#750  -  []  244.64 241.15 90 top
NOREF#751  -  []  169.52 207.27 90 top
NOREF#752  -  []  155.17 281.32 0 top
NOREF#753  -  []  231.11 200.17 90 top
NOREF#754  -  []  166.32 269.17 0 top
NOREF#755  -  []  157.18 176.17 90 top
NOREF#756  -  []  283.97 214.54 0 top
NOREF#757  -  []  237.59 175.77 0 top
NOREF#758  -  []  215.24 201.55 90 top
NOREF#759  -  []  274.39 216.17 90 top
NOREF#760  -  []  122.57 291.95 0 top
NOREF#761  -  []  239.4 204.45 90 top
NOREF#762  -  []  136.63 232.23 0 top
NOREF#763  -  []  232.51 175.77 0 top
NOREF#764  -  []  191.87 456.29 0 top
NOREF#765  -  []  188.95 266.89 0 top
NOREF#766  -  []  196.81 232.54 0 top
NOREF#767  -  []  244.95 207.27 90 top
NOREF#768  -  []  271.79 251.93 0 top
NOREF#769  -  []  236.33 167.9 90 top
NOREF#770  -  []  267.77 252.78 0 top
NOREF#771  -  []  173.64 299.09 0 top
NOREF#772  -  []  155.17 221.32 0 top
NOREF#773  -  []  244.76 392.33 90 top
NOREF#774  -  []  179.73 238.35 0 top
NOREF#775  -  []  132.64 204.47 0 top
NOREF#776  -  []  203.97 274.54 0 top
NOREF#777  -  []  144.16 256.43 90 top
NOREF#778  -  []  228.81 255.7 90 top
NOREF#779  -  []  153.39 253.03 90 top
NOREF#780  -  []  106.68 148.34 0 top
NOREF#781  -  []  278.64 233.37 90 top
NOREF#782  -  []  90.49 457.2 0 top
NOREF#783  -  []  163.84 260.97 90 top
NOREF#784  -  []  131.26 244.35 0 top
NOREF#785  -  []  192.63 233.69 0 top
NOREF#786  -  []  272.11 171.4 0 top
NOREF#787  -  []  138.83 232.23 0 top
NOREF#788  -  []  283.97 268.95 0 top
NOREF#789  -  []  232.25 272.17 90 top
NOREF#790  -  []  248.42 264.78 90 top
NOREF#791  -  []  258.95 206.12 0 top
NOREF#792  -  []  155.15 236.17 90 top
NOREF#793  -  []  277.37 240.3 90 top
NOREF#794  -  []  275.05 274.25 0 top
NOREF#795  -  []  190.15 266.89 90 top
NOREF#796  -  []  152.72 252.5 0 top
NOREF#797  -  []  312.52 456.29 0 top
NOREF#798  -  []  211.25 244.35 0 top
NOREF#799  -  []  274.39 226.59 90 top
NOREF#800  -  []  206.32 209.17 0 top
NOREF#801  -  []  255.24 261.55 90 top
NOREF#802  -  []  202.2 178.35 0 top
NOREF#803  -  []  190.97 255.7 90 top
NOREF#804  -  []  199.27 265.58 0 top
NOREF#805  -  []  189.84 213.7 90 top
NOREF#806  -  []  186.7 237.02 90 top
NOREF#807  -  []  124.61 234.89 90 top
NOREF#808  -  []  154.84 18.69 90 top
NOREF#809  -  []  147.45 209.24 0 top
NOREF#810  -  []  157.81 389.27 90 top
NOREF#811  -  []  193.27 198.18 0 top
NOREF#812  -  []  186.43 282.49 90 top
NOREF#813  -  []  199.27 204.78 90 top
NOREF#814  -  []  188.32 253.35 0 top
NOREF#815  -  []  157.04 184.35 0 top
NOREF#816  -  []  265.41 226.99 90 top
NOREF#817  -  []  155.17 212.18 0 top
NOREF#818  -  []  106.68 148.34 90 top
NOREF#819  -  []  260.95 268.91 90 top
NOREF#820  -  []  208.54 262.09 0 top
NOREF#821  -  []  168.54 260.64 90 top
NOREF#822  -  []  154.62 247.68 90 top
NOREF#823  -  []  183.89 245.24 90 top
NOREF#824  -  []  159.44 179.15 0 top
NOREF#825  -  []  270.97 190.88 90 top
NOREF#826  -  []  317.15 392.33 90 top
NOREF#827  -  []  147.43 278.27 90 top
NOREF#828  -  []  261.59 248.12 0 top
NOREF#829  -  []  281.41 227.9 90 top
NOREF#830  -  []  168.54 267.5 90 top
NOREF#831  -  []  149.29 286.59 90 top
NOREF#832  -  []  274.39 286.59 90 top
NOREF#833  -  []  179.08 265.79 0 top
NOREF#834  -  []  152.66 226.35 90 top
NOREF#835  -  []  153.95 251.93 0 top
NOREF#836  -  []  155.17 212.18 90 top
NOREF#837  -  []  127.95 226.12 90 top
NOREF#838  -  []  196.1 280.99 90 top
NOREF#839  -  []  186.01 255.7 90 top
NOREF#840  -  []  268.19 187.71 0 top
NOREF#841  -  []  263.89 245.24 90 top
NOREF#842  -  []  215.84 202.57 90 top
NOREF#843  -  []  228.81 190.88 90 top
NOREF#844  -  []  175.24 261.55 90 top
NOREF#845  -  []  214.07 270.89 90 top
NOREF#846  -  []  232.72 192.78 0 top
NOREF#847  -  []  188.32 193.35 0 top
NOREF#848  -  []  273.18 244.35 0 top
NOREF#849  -  []  276.8 225.06 90 top
NOREF#850  -  []  228.35 277.95 90 top
NOREF#851  -  []  185.61 192.78 0 top
NOREF#852  -  []  214.07 210.89 90 top
NOREF#853  -  []  159.4 213.09 90 top
NOREF#854  -  []  243.97 268.95 0 top
NOREF#855  -  []  116.51 14.59 90 top
NOREF#856  -  []  159.72 214.65 90 top
NOREF#857  -  []  208.94 221.73 0 top
NOREF#858  -  []  156.57 185.63 0 top
NOREF#859  -  []  161.44 244.35 0 top
NOREF#860  -  []  163.92 289.94 0 top
NOREF#861  -  []  271.79 191.93 0 top
NOREF#862  -  []  159.4 262.09 0 top
NOREF#863  -  []  139.73 178.35 0 top
NOREF#864  -  []  229.72 275.77 0 top
NOREF#865  -  []  236.52 285.69 0 top
NOREF#866  -  []  246.32 202.32 0 top
NOREF#867  -  []  277.04 244.35 0 top
NOREF#868  -  []  150.77 213.37 90 top
NOREF#869  -  []  140.95 266.12 90 top
NOREF#870  -  []  254.09 260.42 90 top
NOREF#871  -  []  267.45 269.24 0 top
NOREF#872  -  []  217.25 236.5 90 top
NOREF#873  -  []  219.08 265.79 0 top
NOREF#874  -  []  223.36 187.38 0 top
NOREF#875  -  []  195.15 236.17 90 top
NOREF#876  -  []  179.73 178.35 0 top
NOREF#877  -  []  159.27 201.77 0 top
NOREF#878  -  []  256.83 287.03 0 top
NOREF#879  -  []  196.52 225.69 0 top
NOREF#880  -  []  240.11 18.69 0 top
NOREF#881  -  []  186.01 195.7 90 top
NOREF#882  -  []  284.95 207.27 90 top
NOREF#883  -  []  249.52 267.27 90 top
NOREF#884  -  []  204.95 210.32 90 top
NOREF#885  -  []  197.25 256.75 0 top
NOREF#886  -  []  271.91 251.6 90 top
NOREF#887  -  []  273.6 276.55 0 top
NOREF#888  -  []  294.09 260.42 90 top
NOREF#889  -  []  156.02 181.47 0 top
NOREF#890  -  []  143.49 197.85 90 top
NOREF#891  -  []  279.27 265.58 0 top
NOREF#892  -  []  155.58 202.67 90 top
NOREF#893  -  []  109.55 389.27 90 top
NOREF#894  -  []  151.98 220.75 90 top
NOREF#895  -  []  170.89 269.17 0 top
NOREF#896  -  []  153.39 197.85 90 top
NOREF#897  -  []  147.77 181.47 0 top
NOREF#898  -  []  243.84 260.97 90 top
NOREF#899  -  []  225.42 214.72 90 top
NOREF#900  -  []  267.77 181.47 0 top
NOREF#901  -  []  288.42 201.77 0 top
NOREF#902  -  []  269.84 213.7 90 top
NOREF#903  -  []  159.4 200.64 90 top
NOREF#904  -  []  148.32 253.35 0 top
NOREF#905  -  []  232.25 218.02 90 top
NOREF#906  -  []  193.95 251.93 0 top
NOREF#907  -  []  219.08 205.79 0 top
NOREF#908  -  []  263.89 185.24 90 top
NOREF#909  -  []  215.59 16.49 0 top
NOREF#910  -  []  261.55 205.11 90 top
NOREF#911  -  []  150.88 228.6 90 top
NOREF#912  -  []  272.25 222.59 90 top
NOREF#913  -  []  264.16 191.6 90 top
NOREF#914  -  []  268.99 191.93 0 top
NOREF#915  -  []  239.4 208.95 0 top
NOREF#916  -  []  231.19 278.07 0 top
NOREF#917  -  []  196.8 274.65 90 top
NOREF#918  -  []  235.17 216.75 90 top
NOREF#919  -  []  161.75 212.22 0 top
NOREF#920  -  []  267.9 265.84 90 top
NOREF#921  -  []  135.11 261.22 90 top
NOREF#922  -  []  237.71 233.69 90 top
NOREF#923  -  []  211.05 289.49 0 top
NOREF#924  -  []  270.77 213.37 90 top
NOREF#925  -  []  95.33 20.69 90 top
NOREF#926  -  []  100.95 17.15 0 top
NOREF#927  -  []  204.95 272.86 90 top
NOREF#928  -  []  243.97 213.09 90 top
NOREF#929  -  []  143.49 257.85 90 top
NOREF#930  -  []  270.6 173.69 0 top
NOREF#931  -  []  236.79 231.3 0 top
NOREF#932  -  []  157.25 196.75 0 top
NOREF#933  -  []  261.03 207.69 90 top
NOREF#934  -  []  231.24 193.03 90 top
NOREF#935  -  []  129.49 220.89 0 top
NOREF#936  -  []  147.03 231.4 0 top
NOREF#937  -  []  173.64 239.09 0 top
NOREF#938  -  []  235.17 276.75 0 top
NOREF#939  -  []  173.78 207.01 0 top
NOREF#940  -  []  272.66 226.35 90 top
NOREF#941  -  []  149.12 256.43 90 top
NOREF#942  -  []  170.89 262.32 0 top
NOREF#943  -  []  232.63 233.69 0 top
NOREF#944  -  []  128.46 18.69 0 top
NOREF#945  -  []  146.96 251.6 90 top
NOREF#946  -  []  156.52 225.69 0 top
NOREF#947  -  []  189.84 219.54 90 top
NOREF#948  -  []  241.84 235.2 0 top
NOREF#949  -  []  279.72 214.65 90 top
NOREF#950  -  []  281.12 248.11 90 top
NOREF#951  -  []  275.17 272.17 90 top
NOREF#952  -  []  239.72 274.65 90 top
NOREF#953  -  []  247.04 239.09 0 top
NOREF#954  -  []  235.15 236.17 90 top
NOREF#955  -  []  164.32 291.95 90 top
NOREF#956  -  []  164.61 234.89 90 top
NOREF#957  -  []  195.05 223.39 0 top
NOREF#958  -  []  149.12 191.6 90 top
NOREF#959  -  []  275.92 190.88 90 top
NOREF#960  -  []  190.77 279.22 90 top
NOREF#961  -  []  191.79 196.75 0 top
NOREF#962  -  []  233.76 190.88 90 top
NOREF#963  -  []  190.6 233.69 0 top
NOREF#964  -  []  230.98 184.35 0 top
NOREF#965  -  []  230.6 173.69 0 top
NOREF#966  -  []  157.04 244.35 0 top
NOREF#967  -  []  215.24 261.55 90 top
NOREF#968  -  []  219.08 263.76 0 top
NOREF#969  -  []  218.35 264.47 0 top
NOREF#970  -  []  221.55 209.94 90 top
NOREF#971  -  []  279.4 267.5 90 top
NOREF#972  -  []  196.7 181.72 90 top
NOREF#973  -  []  141.43 285.38 90 top
NOREF#974  -  []  168.42 204.78 90 top
NOREF#975  -  []  191.19 228.49 0 top
NOREF#976  -  []  273.18 282.26 90 top
NOREF#977  -  []  221.55 205.11 90 top
NOREF#978  -  []  232.13 220.09 0 top
NOREF#979  -  []  190.77 273.37 90 top
NOREF#980  -  []  180.95 206.12 90 top
NOREF#981  -  []  138.83 292.23 0 top
NOREF#982  -  []  148.99 256.75 0 top
NOREF#983  -  []  150.98 184.35 0 top
NOREF#984  -  []  202.2 238.35 0 top
NOREF#985  -  []  150.6 233.69 0 top
NOREF#986  -  []  178.97 18.69 0 top
NOREF#987  -  []  259.08 268.59 0 top
NOREF#988  -  []  195.58 262.67 90 top
NOREF#989  -  []  254.43 232.23 0 top
NOREF#990  -  []  226.01 255.7 90 top
NOREF#991  -  []  264.26 456.29 0 top
NOREF#992  -  []  176.26 263.76 90 top
NOREF#993  -  []  236.52 276.55 0 top
NOREF#994  -  []  91.03 148.19 0 top
NOREF#995  -  []  153.18 282.26 90 top
NOREF#996  -  []  186.16 193.35 0 top
NOREF#997  -  []  189.84 279.54 0 top
NOREF#998  -  []  155.92 195.7 90 top
NOREF#999  -  []  238.91 232.21 90 top
NOREF#1000  -  []  202.2 178.35 0 top
NOREF#1001  -  []  233.18 277.69 90 top
NOREF#1002  -  []  265.61 257.6 0 top
NOREF#1003  -  []  0 382.27 0 top
NOREF#1004  -  []  276.7 197.85 90 top
NOREF#1005  -  []  218.95 201.55 0 top
NOREF#1006  -  []  143.36 193.35 0 top
NOREF#1007  -  []  279.06 238.07 0 top
NOREF#1008  -  []  191.24 257.85 90 top
NOREF#1009  -  []  197.37 240.3 90 top
NOREF#1010  -  []  145.42 214.72 90 top
NOREF#1011  -  []  211.21 294.24 90 top
NOREF#1012  -  []  225.09 197.49 90 top
NOREF#1013  -  []  191.91 251.6 90 top
NOREF#1014  -  []  186.28 257.85 90 top
NOREF#1015  -  []  176.55 194.49 90 top
NOREF#1016  -  []  201.41 227.9 90 top
NOREF#1017  -  []  266.28 257.85 90 top
NOREF#1018  -  []  213.64 239.09 0 top
NOREF#1019  -  []  164.44 232.28 90 top
NOREF#1020  -  []  201.44 244.35 0 top
NOREF#1021  -  []  273.56 173.37 90 top
NOREF#1022  -  []  192.13 220.09 0 top
NOREF#1023  -  []  191.91 196.43 90 top
NOREF#1024  -  []  262.03 289.03 90 top
NOREF#1025  -  []  147.43 278.27 0 top
NOREF#1026  -  []  188.95 206.89 0 top
NOREF#1027  -  []  237.04 184.35 0 top
NOREF#1028  -  []  220.95 264.09 90 top
NOREF#1029  -  []  231.76 167.33 0 top
NOREF#1030  -  []  261.85 292.49 0 top
NOREF#1031  -  []  184.04 256.75 0 top
NOREF#1032  -  []  243.92 229.94 0 top
NOREF#1033  -  []  150.98 244.35 0 top
NOREF#1034  -  []  229.24 245.31 90 top
NOREF#1035  -  []  173.24 261.55 0 top
NOREF#1036  -  []  289.52 260.42 90 top
NOREF#1037  -  []  242.85 297.22 0 top
NOREF#1038  -  []  146.96 196.43 90 top
NOREF#1039  -  []  166.32 202.32 0 top
NOREF#1040  -  []  263.36 187.38 0 top
NOREF#1041  -  []  279.27 214.21 0 top
NOREF#1042  -  []  190.77 219.22 90 top
NOREF#1043  -  []  164.95 272.86 90 top
NOREF#1044  -  []  277.71 172.86 0 top
NOREF#1045  -  []  155.17 221.32 90 top
NOREF#1046  -  []  221.6 17.15 0 top
NOREF#1047  -  []  173.62 289.09 90 top
NOREF#1048  -  []  243.04 176.5 90 top
NOREF#1049  -  []  176.72 18.69 0 top
NOREF#1050  -  []  211.21 234.89 90 top
NOREF#1051  -  []  164.95 267.27 90 top
NOREF#1052  -  []  236.7 193.03 90 top
NOREF#1053  -  []  268.81 255.7 90 top
NOREF#1054  -  []  236.45 247.71 0 top
NOREF#1055  -  []  236.57 182.05 0 top
NOREF#1056  -  []  196.33 167.9 90 top
NOREF#1057  -  []  275.68 233.69 90 top
NOREF#1058  -  []  216.38 204.09 90 top
NOREF#1059  -  []  213.64 299.09 0 top
NOREF#1060  -  []  228.78 222.65 0 top
NOREF#1061  -  []  276.54 227 0 top
NOREF#1062  -  []  199.4 270.55 90 top
NOREF#1063  -  []  223.36 198.18 0 top
NOREF#1064  -  []  198.47 82.65 0 top
NOREF#1065  -  []  274.07 251.6 90 top
NOREF#1066  -  []  227.99 238.35 0 top
NOREF#1067  -  []  135.11 201.22 90 top
NOREF#1068  -  []  145.61 254.08 0 top
NOREF#1069  -  []  164.61 234.24 90 top
NOREF#1070  -  []  288.54 200.64 90 top
NOREF#1071  -  []  184.16 191.6 90 top
NOREF#1072  -  []  269.84 284.11 90 top
NOREF#1073  -  []  155.05 283.39 0 top
NOREF#1074  -  []  203.97 207.5 90 top
NOREF#1075  -  []  279.4 268.95 0 top
NOREF#1076  -  []  276.02 252.78 0 top
NOREF#1077  -  []  279.27 211.67 0 top
NOREF#1078  -  []  270.97 195.7 90 top
NOREF#1079  -  []  152.13 274.25 0 top
NOREF#1080  -  []  222.03 289.03 90 top
NOREF#1081  -  []  207.95 226.12 90 top
NOREF#1082  -  []  152.25 272.17 90 top
NOREF#1083  -  []  175.02 208.14 90 top
NOREF#1084  -  []  225.41 273.02 90 top
NOREF#1085  -  []  216.55 280.49 0 top
NOREF#1086  -  []  239.22 195.7 90 top
NOREF#1087  -  []  138.35 207.01 0 top
NOREF#1088  -  []  132.55 224.49 0 top
NOREF#1089  -  []  164.95 210.32 90 top
NOREF#1090  -  []  277.71 232.86 0 top
NOREF#1091  -  []  283.97 202.09 0 top
NOREF#1092  -  []  239.4 272 0 top
NOREF#1093  -  []  164.61 294.89 90 top
NOREF#1094  -  []  256.63 232.23 0 top
NOREF#1095  -  []  168.42 207.82 90 top
NOREF#1096  -  []  221.55 207.14 90 top
NOREF#1097  -  []  247.98 226.38 90 top
NOREF#1098  -  []  159.27 261.77 0 top
NOREF#1099  -  []  132.26 237.5 0 top
NOREF#1100  -  []  281.75 274.76 0 top
NOREF#1101  -  []  239.24 184.35 0 top
NOREF#1102  -  []  208.54 204.45 90 top
NOREF#1103  -  []  244.95 260.42 90 top
NOREF#1104  -  []  189.24 245.31 90 top
NOREF#1105  -  []  157.5 185.31 90 top
NOREF#1106  -  []  147.8 264.99 90 top
